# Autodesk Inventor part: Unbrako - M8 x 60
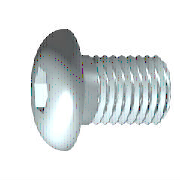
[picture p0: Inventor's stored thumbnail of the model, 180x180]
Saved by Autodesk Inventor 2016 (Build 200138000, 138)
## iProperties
IsCustomPart: 0
Created: 2015-02
Part Number: Unbrako - M8 x 60
Material: Steel, Mild
Description: Hexagon Socket Button Head Cap Screw
Document SubType Name: Modeling
Standard: Unbrako
Designer: stank
Standards Organization: AS
Language: en-US
Size Designation: M8 x 60
Categories: <MemberInstance><Categories><Category DisplayName="Fasteners" InternalName="e4da775c-781d-43d5-af7c-5136215cf5a6" Mnemonic="FSTN"><Category DisplayName="Bolts"
Density: 7.85 g/cm^3
Appearance: Semi-Polished
Mass: 27.9259 g
Surface Area: 19.9507 cm^2
Volume: 3.55744 cm^3
Author: stank
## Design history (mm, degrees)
sketch "Sketch1"
  geometry: L1 (-0.133, 0)-(60, 0); L2 (60, 0)-(60, 4); L3 (60, 4)-(3.125, 4); L4 (3.125, 4)-(2.358, 4); L5 (2.358, 4)-(0, 4); L6 (0, 4)-(0, 7); L7 (0, 7)-(-4.4, 7); L8 (-4.4, 7)-(-4.4, 2.887); L9 (-4.4, 2.887)-(-1.8, 2.887); L10 (-1.8, 2.887)-(-0.133, 0); L11 (-21, 0)-(56, 0) reference; L12 (0, -1.6)-(0, 9.6) reference; L13 (3.125, 4)-(0, 4)
  constraints: 22 end point, 6 parallel, 2 collinear, 2 perpendicular, 1 horizontal, 1 midpoint
  dimensions: "d1" = 56.875 distance from line of L3.end L2 (= GEL); "d2" = 0.76691 distance of L4.end L3.end (computed from GAL); "d3" = 4.4 distance between parallel lines of L8 L6 (= KOH); "d4" = 2.6 distance of L8.end L9.end (= INTI); "d5" = 60 deg angle of L10 L1; "d6" = 8 diameter of L3 L1 (= GD); "d7" = 8 diameter of L5 L1 (= BDM); "d8" = 5.7735 diameter of L9 L1 (= 1.1547 x SW); "d9" = 14 diameter of L7 L1 (= KOD); "d26" = 60 distance between parallel lines of L12 L2 (= NLG)
revolve "Body" sketch "Sketch1" stored, may be unused: angle "d10" = 90 deg
sketch "Sketch2"
  geometry: L1 (0, -9.8)-(0, 9.8) reference; L2 (-9.8, 0)-(9.8, 0) reference; L3 (2.887, 0)-(1.443, -2.5); L4 (1.443, -2.5)-(-1.443, -2.5); L5 (-1.443, -2.5)-(-2.887, 0); L6 (-2.887, 0)-(-1.443, 2.5); L7 (-1.443, 2.5)-(1.443, 2.5); L8 (1.443, 2.5)-(2.887, 0); 2 further points
  constraints: 12 end point, 1 coincident, 1 horizontal alignment, 1 point on line, 12 other
extrude "Slot" join sketch "Sketch2" stored distance "d11" = 10; taper "d12" = 0 deg
workplane "Work Plane1"
fillet "Fillet2" dims "d30" = 0.1 (= R)
body "Solid1"
fillet "Fillet1" dims "d17" = 2.6 (= RR)
feature "Thread" dims "d13" = 56.875 (= GEL), "d14" = 0
chamfer "Chamfer1" distance "d15" = 0.76681 (= -0.5 x SPD + 0.5 x GD); stored, may be unused: second distance "d16" = 0.76681 (= GUL), angle "d27" = 45 deg
other parameters: "GD" = 8 (= NND) [user parameter; used in 2 equation terms], "NLG" = 60 [user parameter; used in 1 equation term], "GEL" = 56.875 [user parameter; used in 2 equation terms], "KOD" = 14 [user parameter; used in 1 equation term], "KOH" = 4.4 [user parameter; used in 1 equation term], "INTI" = 2.6 [user parameter; used in 2 equation terms], "GAL" = 0.76681 (= 0.61345 x PTC) [user parameter; used in 1 equation term], "GUL" = 0.76681 (= 0.61345 x PTC) [user parameter; used in 1 equation term], "BDM" = 8 (= NND) [user parameter; used in 1 equation term], "SW" = 5 [user parameter; used in 2 equation terms], "RR" = 2.6 (= INTI) [user parameter; used in 1 equation term], "SPD" = 6.46637 (= NND - 1.2269 x PTC) [user parameter; used in 1 equation term], "d19" = 0, "d28" = 0, "d29" = 0, "R" = 0.1 [user parameter; used in 1 equation term], "KR" = 7.5 [user parameter], "GD1" = 6.46637 (= THREADDIA - 1.2269 x PTC) [user parameter], "THREADDIA" = 8 [user parameter; used in 1 equation term], "FAWI" = 45 deg [user parameter], "TPU" = 8 (computed from PTC) [user parameter], "PTC" = 1.25 [user parameter; used in 5 equation terms], "KOH1" = 2.6 [user parameter], "NND" = 8 [user parameter; used in 3 equation terms], "TOA" = 30 deg [user parameter], "E0" = 5.775 (= 1.155 x SW) [user parameter]
